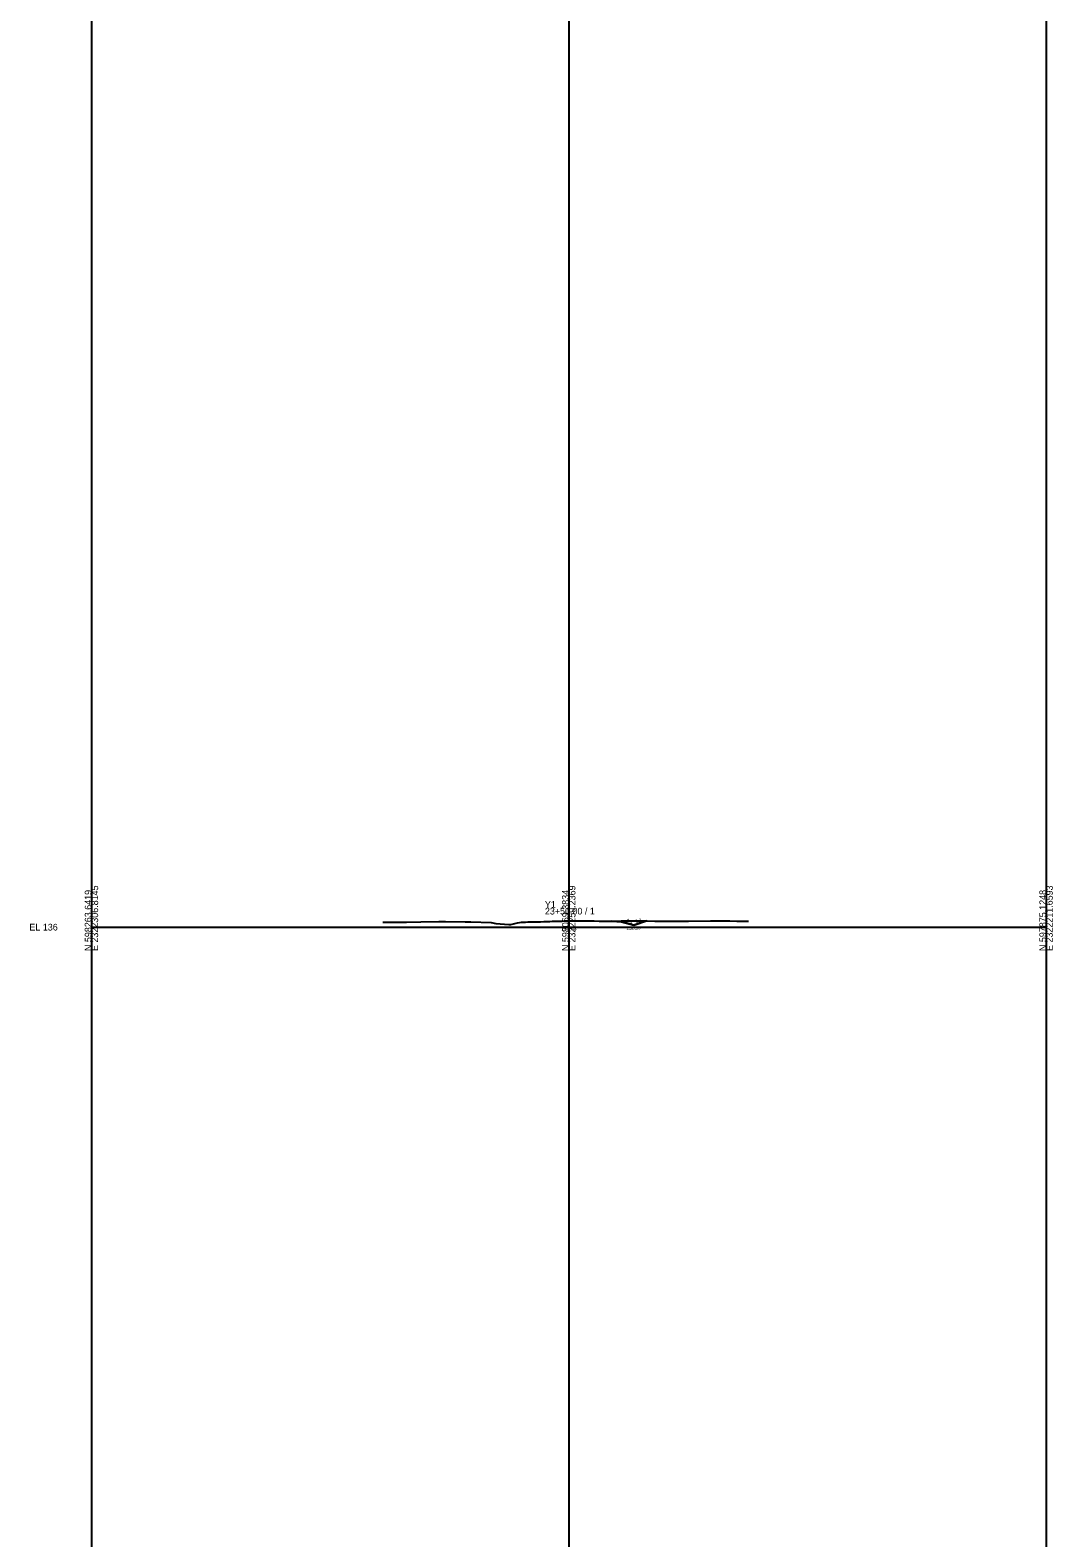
# Model space of a CAD drawing. Extents: x -26 to 2321974, y -203 to 598218.
# Drawn here: x 1974 to 2403, y 6744 to 7376 of the extents above; entities that cross this region are included whole.
import ezdxf

# ---------------------------------------------------------------- set-up
doc = ezdxf.new("R2010")
doc.units = 0
for name, color, linetype in [('Exist CMT Pavement', 7, 'Continuous'), ('Exist Cross Section Cell', 7, 'Continuous'), ('Exist XS Center Line Elevation Label', 7, 'Continuous'), ('Exist XS Ground Line', 7, 'Continuous'), ('Prop CMT Slope Grass', 7, 'Continuous'), ('Prop XS Ditch Standard Text', 7, 'Continuous'), ('Prop XS Earthwork Shape', 7, 'Continuous'), ('Prop XS Exc Vertical Line 1', 7, 'Continuous'), ('Prop XS Exc Vertical Line 2', 7, 'Continuous'), ('Prop XS Exc Vertical Line 3', 7, 'Continuous'), ('Prop XS Side Slope Text', 7, 'Continuous')]:
    doc.layers.add(name, color=color, linetype=linetype)

msp = doc.modelspace()

# ---------------------------------------------------------------- linework, layer by layer
at = {"layer": 'Exist CMT Pavement'}
for points in [[(2199.9, 7002.63), (2199.9, 7002.73), (2200, 7002.73), (2200, 7002.63)], [(2200, 7002.63), (2200, 7002.73), (2200.1, 7002.73), (2200.1, 7002.63)]]:
    msp.add_lwpolyline(points, dxfattribs=at)
at = {"layer": 'Exist Cross Section Cell'}
for p, q in [((2200, 7000), (2200, 7008.11)), ((2000, 7000), (2200, 7000)), ((2200, 7000), (2400, 7000))]:
    msp.add_line(p, q, dxfattribs=at)
at = {"layer": 'Exist XS Ground Line'}
msp.add_lwpolyline([(2122.11, 7002.13), (2123.56, 7002.15), (2126.29, 7002.05), (2127.72, 7002.08), (2131.98, 7002.05), (2138.02, 7002.17), (2145.62, 7002.32), (2148.31, 7002.31), (2156.63, 7002.28), (2158.61, 7002.27), (2158.95, 7002.24), (2167.46, 7001.9), (2169.38, 7001.6), (2174.86, 7001.15), (2175.72, 7001.06), (2178.55, 7001.87), (2180.21, 7002.13), (2181.88, 7002.14), (2182.85, 7002.17), (2183.8, 7002.18), (2185.6, 7002.21), (2186.9, 7002.25), (2188.1, 7002.28), (2189.49, 7002.33), (2190.6, 7002.37), (2192.08, 7002.42), (2193.1, 7002.46), (2193.86, 7002.49), (2194.34, 7002.51), (2194.89, 7002.52), (2195.6, 7002.53), (2197.26, 7002.57), (2198.11, 7002.59), (2200, 7002.63), (2200.61, 7002.64), (2202.44, 7002.67), (2203.11, 7002.68), (2203.95, 7002.68), (2204.8, 7002.69), (2205.25, 7002.68), (2205.61, 7002.68), (2207.62, 7002.65), (2208.11, 7002.65), (2210.21, 7002.61), (2210.61, 7002.6), (2212.8, 7002.54), (2213.12, 7002.53), (2215.84, 7002.5), (2216.55, 7002.5), (2217.75, 7002.49), (2218.25, 7002.5), (2218.78, 7002.51), (2219.73, 7002.52), (2221.9, 7002.61), (2223.53, 7002.6), (2225.22, 7002.65), (2225.87, 7002.65), (2227.32, 7002.7), (2230.16, 7002.66), (2232.81, 7002.63), (2236.08, 7002.54), (2244.22, 7002.51), (2245.91, 7002.49), (2250.14, 7002.58), (2259.37, 7002.59), (2267.51, 7002.6), (2270.48, 7002.54), (2271.16, 7002.53), (2271.64, 7002.54), (2275.26, 7002.51)], dxfattribs=at)
at = {"layer": 'Prop CMT Slope Grass'}
for p, q in [((2218.1, 7002.5), (2222.1, 7002.18)), ((2222.1, 7002.18), (2227.29, 7000.88)), ((2227.29, 7000.88), (2232.56, 7002.64))]:
    msp.add_line(p, q, dxfattribs=at)
at = {"layer": 'Prop XS Earthwork Shape'}
for points in [[(2199.9, 7002.73), (2200, 7002.73), (2200, 7002.63), (2199.9, 7002.63)], [(2199.9, 7002.73), (2200, 7002.73), (2200, 7002.63), (2199.9, 7002.63)], [(2200, 7002.73), (2200, 7002.63), (2200.1, 7002.63), (2200.1, 7002.73)], [(2200, 7002.73), (2200, 7002.63), (2200.1, 7002.63), (2200.1, 7002.73)], [(2200, 7002.73), (2200.1, 7002.73), (2200.1, 7002.63), (2200, 7002.63)], [(2218.1, 7002.5), (2218.25, 7002.5), (2218.78, 7002.51), (2219.73, 7002.52), (2221.9, 7002.61), (2223.53, 7002.6), (2225.22, 7002.65), (2225.87, 7002.65), (2227.32, 7002.7), (2230.16, 7002.66), (2232.56, 7002.64), (2227.29, 7000.88), (2222.1, 7002.18)], [(2218.1, 7002.5), (2218.25, 7002.5), (2218.78, 7002.51), (2219.73, 7002.52), (2221.9, 7002.61), (2223.53, 7002.6), (2225.22, 7002.65), (2225.87, 7002.65), (2227.32, 7002.7), (2230.16, 7002.66), (2232.56, 7002.64), (2227.29, 7000.88), (2222.1, 7002.18)], [(2218.1, 7002.5), (2218.25, 7002.5), (2218.78, 7002.51), (2219.73, 7002.52), (2221.9, 7002.61), (2223.53, 7002.6), (2225.22, 7002.65), (2225.87, 7002.65), (2227.32, 7002.7), (2230.16, 7002.66), (2232.56, 7002.64), (2227.29, 7000.88), (2222.1, 7002.18)]]:
    msp.add_lwpolyline(points, close=True, dxfattribs=at)
at = {"layer": 'Prop XS Exc Vertical Line 1'}
msp.add_line((2000, 9901.81), (2000, -202.52), dxfattribs=at)
at = {"layer": 'Prop XS Exc Vertical Line 2'}
msp.add_line((2200, 9901.81), (2200, -202.52), dxfattribs=at)
at = {"layer": 'Prop XS Exc Vertical Line 3'}
msp.add_line((2400, 9901.81), (2400, -202.52), dxfattribs=at)

# ---------------------------------------------------------------- texts
at = {"layer": 'Exist Cross Section Cell'}
for s, p in [('E 2322306.8145', (2002.8, 6990)), ('E 2322259.2369', (2202.8, 6990)), ('E 2322211.6593', (2402.8, 6990)), ('N 598263.6419', (2000, 6990)), ('N 598069.3834', (2200, 6990)), ('N 597875.1248', (2400, 6990))]:
    msp.add_text(s, height=2.8, rotation=90, dxfattribs=at).set_placement(p)
for s, p in [('Y1', (2190, 7008.11)), ('23+50.00 / 1', (2190, 7005.31)), ('EL 136', (1974, 6998.6))]:
    msp.add_text(s, height=2.8, dxfattribs=at).set_placement(p)
at = {"layer": 'Exist XS Center Line Elevation Label'}
msp.add_text('138.63', height=1.5, dxfattribs=at).set_placement((2196.91, 6998.63))
at = {"layer": 'Prop XS Ditch Standard Text'}
msp.add_text('136.97', height=1.5, dxfattribs=at).set_placement((2224.13, 6998.86))
at = {"layer": 'Prop XS Side Slope Text'}
for s, rotation, p in [('3:1', 18.41776, (2228.09, 7001.53)), ('4:1', 341.58224, (2223.85, 7002.32))]:
    msp.add_text(s, height=1.5, rotation=rotation, dxfattribs=at).set_placement(p)

doc.saveas('drawing.dxf')
